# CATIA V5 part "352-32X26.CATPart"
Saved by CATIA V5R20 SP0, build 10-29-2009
Part number: 352-32X26
Definition: NONE
Nomenclature: 352-32X26
Source: Unknown
Description: 352-32X26
Bounding box of the stored display mesh (mm): x 0 to 26, y -20 to 20, z -20 to 20
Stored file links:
  C:\Users\Utente\Desktop\IO LAVORO\3D X SITO CF\X SITO\PLASTICA\352\352-32X26.CATPart

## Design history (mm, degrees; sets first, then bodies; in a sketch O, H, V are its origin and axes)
Body1 "352-32X26" (main body)
  Solid1: solid without history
